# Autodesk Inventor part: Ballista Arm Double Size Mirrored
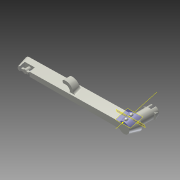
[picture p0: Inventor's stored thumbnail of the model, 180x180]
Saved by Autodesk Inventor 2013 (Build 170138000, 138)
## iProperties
Created: 2013-06
Part Number: Ballista Arm Double Size Mirrored
Material: Generic
Document SubType Name: Modeling
Designer: merrill
Density: 1 g/cm^3
Mass: 4.71484 g
Surface Area: 31.3441 cm^2
Volume: 4.71484 cm^3
d7: 1.500 ul
d0_2: 145.00 deg
d1_1: 2.000 in
d2_1: 0.200 in
d3_1: 15.00 deg
d4_1: 0.300 in
d5_1: 0.00 deg
d6_1: 0.100 in
d9_1: 0.200 in
d12_1: 0.075 in
d13_1: 0.025 in
d14_1: 0.100 in
d15_1: 0.00 deg
d18_1: 0.100 in
d20_1: 0.100 in
d21_1: 20.00 deg
d22_1: 0.075 in
d24_1: 0.100 in
d25_1: 0.200 in
d26_1: 0.250 in
d27_1: 0.100 in
d28_1: 0.00 deg
d31_1: 0.150 in
d33_1: 0.040 in
d34_1: 0.040 in
d35_1: 0.00 deg
d36_1: 0.010 in
d37_1: 0.010 in
d38_1: 0.160 in
d39_1: 0.040 in
d56_1: -0.100 in
d57_1: 0.00 deg
d58_1: 0.045 in
d67_1: 0.050 in
d68_1: 0.00 deg
d69_1: 0.040 in
d70_1: 0.030 in
d71_1: 0.050 in
d72_1: 0.020 in
d74_1: 90.00 deg
Author: merrill
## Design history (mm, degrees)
derived "Ballista Arm Double Size.ipt"
  sketch "Sketch23_1"
    geometry: 3 further points; 1 other entity
    constraints: 1 horizontal alignment
  sketch "Sketch20_1"
    geometry: 2 further points; 1 other entity
    constraints: 1 vertical alignment
  workplane "Work Plane2_1"
  workplane "Work Plane3_1"
  workaxis "Work Axis1_1"
  workaxis "Work Axis3_1"
feature "Solid2::Ballista Arm Double Size.ipt"
tag "TaggingFeature1"
body "Solid1"
other parameters: "d7" = 1.5, "d0_2" = 145 deg, "d1_1" = 50.8, "d2_1" = 5.08, "d3_1" = 15 deg, "d4_1" = 7.62, "d5_1" = 0 deg, "d6_1" = 2.54, "d9_1" = 5.08, "d12_1" = 1.905, "d13_1" = 0.635, "d14_1" = 2.54, "d15_1" = 0 deg, "d18_1" = 2.54, "d20_1" = 2.54, "d21_1" = 20 deg, "d22_1" = 1.905, "d24_1" = 2.54, "d25_1" = 5.08, "d26_1" = 6.35, "d27_1" = 2.54, "d28_1" = 0 deg, "d31_1" = 3.81, "d33_1" = 1.016, "d34_1" = 1.016, "d35_1" = 0 deg, "d36_1" = 0.254, "d37_1" = 0.254, "d38_1" = 4.064, "d39_1" = 1.016, "d56_1" = -2.54, "d57_1" = 0 deg, "d58_1" = 1.143, "d67_1" = 1.27, "d68_1" = 0 deg, "d69_1" = 1.016, "d70_1" = 0.762, "d71_1" = 1.27, "d72_1" = 0.508, "d74_1" = 90 deg
